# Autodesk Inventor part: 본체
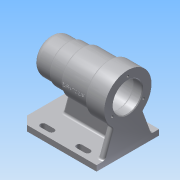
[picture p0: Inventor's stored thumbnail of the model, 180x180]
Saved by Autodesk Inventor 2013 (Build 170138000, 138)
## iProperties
Created: 2017-09
Part Number: 본체
Material: 알루미늄 6061
Document SubType Name: Modeling
Designer: Administrator
Density: 2.71 g/cm^3
Mass: 693.622 g
Surface Area: 713.941 cm^2
Volume: 255.949 cm^3
Author: Administrator
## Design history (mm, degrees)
sketch "스케치1"
  geometry: L1 (-56, 0)-(56, 0); L2 (-56, 0)-(-56, 25); L3 (-56, 25)-(-31, 25); L4 (-31, 25)-(-31, 27); L5 (-31, 27)-(-11, 27); L6 (-11, 27)-(-11, 30); L7 (-11, 30)-(28, 30); L8 (28, 30)-(28, 34); L9 (28, 34)-(56, 34); L10 (56, 34)-(56, 0); 2 further points
  constraints: 20 end point, 7 parallel, 2 perpendicular, 1 coincident, 1 horizontal, 1 midpoint
  dimensions: "d0" = 112 distance of L1.start L1.end; "d3" = 25 distance of L2.end L3.end; "d4" = 45 distance between parallel lines of L6 L2; "d5" = 84 distance between parallel lines of L8 L2; "d6" = 50 diameter of L3 L1; "d7" = 54 diameter of L5 L1; "d8" = 60 diameter of L7 L1; "d9" = 68 diameter of L9 L1
revolve "회전1" sketch "스케치1" stored, may be unused: angle "d10" = 90 deg
node "작업 평면1"
sketch "스케치2"
  geometry: L1 (-56, 45)-(56, 45); L2 (56, 45)-(56, -45); L3 (56, -45)-(-56, -45); L4 (-56, -45)-(-56, 45); L5 (-56, 34)-(-56, -34) reference; 2 further points
  constraints: 8 end point, 2 midpoint, 2 parallel, 1 horizontal, 1 perpendicular
  dimensions: "d12" = 90 distance between parallel lines of L3 L1; "d14" = 112 distance between parallel lines of L2 L4
extrude "돌출1" join sketch "스케치2" distance "d15" = 8; taper "d16" = 0 deg
sketch "스케치3"
  geometry: L1 (90, 8)-(0, 8) reference; L2 (10, 8)-(23.1, 43.992); L3 (80, 8)-(66.9, 43.992); A1 r 34 centre (45, 70) between (23.1, 43.992) and (66.9, 43.992) reference; A2 r 34 centre (45, 70) between (23.1, 43.992) and (66.9, 43.992) reference; 1 further point
  constraints: 4 end point, 4 point on circle, 2 point on line
  dimensions: "d17" = 10 distance of L1.end L2.start; "d18" = 10 distance of L1.start L3.start; "d19" = 110 deg angle of L1 L2; "d20" = 110 deg angle of L1 L3
extrude "돌출2" join sketch "스케치3" distance "d21" = 8; taper "d22" = 0 deg
sketch "스케치4"
  geometry: L1 (-31, -27)-(-11, -27) reference; L2 (56, -62)-(-56, -62) reference; L3 (-24.622, -27)-(-34, -62); L4 (-11, -30)-(28, -30) reference; L5 (28, -34)-(48, -34) reference; L6 (48, -62)-(48, -26.008) reference; L7 (48, -26.008)-(48, -26.008) reference; L8 (48, -26.008)-(48, -62) reference; L9 (28, -34)-(28, 34) reference; L10 (28, -30)-(28, 30) reference; L11 (-11, -30)-(-11, 30) reference; 1 further point
  constraints: 2 end point, 2 point on line
  dimensions: "d25" = 22 distance of L2.end L3.end; "d26" = 105 deg angle of L2 L3
feature "리브1" sketch "스케치4" dims "d27" = 1, "d28" = 8, "d29" = 0, "d30" = 0, "d31" = 1, "d32" = 1
sketch "스케치5"
  geometry: C1 r 10.5 at (45, 70); 1 further point
  constraints: 1 centre point, 1 coincident
  dimensions: "d33" = 21 diameter of C1
extrude "돌출3" cut sketch "스케치5" distance "d35" = 106; taper "d36" = 0 deg
sketch "스케치6"
  geometry: C1 r 16 at (45, 70); 1 further point
  constraints: 1 centre point, 1 coincident
  dimensions: "d37" = 32 diameter of C1
extrude "돌출4" cut sketch "스케치6" distance "d39" = 103; taper "d40" = 0 deg
sketch "스케치7"
  geometry: C1 r 17.5 at (45, 70); 1 further point
  constraints: 1 centre point, 1 coincident
  dimensions: "d41" = 35 diameter of C1
extrude "돌출5" cut sketch "스케치7" distance "d43" = 99; taper "d44" = 0 deg
sketch "스케치8"
  geometry: C1 r 10.5 at (45, 70) reference; C2 r 21 at (45, 70); 1 further point
  constraints: 1 centre point, 1 coincident
  dimensions: "d45" = 42 diameter of C2
extrude "돌출6" cut sketch "스케치8" distance "d47" = 81; taper "d48" = 0 deg
sketch "스케치9"
  geometry: C1 r 27 at (45, 70) reference; C2 r 24 at (45, 70); 1 further point
  constraints: 1 centre point, 1 coincident
  dimensions: "d49" = 48 diameter of C2
extrude "돌출7" cut sketch "스케치9" distance "d51" = 69; taper "d52" = 0 deg
sketch "스케치10"
  geometry: C1 r 10.5 at (45, 70) reference; C2 r 21 at (45, 70); C3 r 24 at (45, 70) reference; 1 further point
  constraints: 1 centre point, 1 coincident
  dimensions: "d53" = 42 diameter of C2
extrude "돌출8" join sketch "스케치10" distance "d55" = 15; taper "d56" = 0 deg
sketch "스케치11" dims "d57" = 52
  geometry: 3 further points
  constraints: 2 vertical alignment, 1 coincident, 2 other
hole "구멍1" sketch "스케치11" at (45, 96) diameter "d59" = 3.242; stored, may be unused: countersink angle "d63" = 90 deg, drill point angle "d65" = 120 deg; dims "d60" = 8, "d61" = 4, "d62" = 2, "d64" = 11
chamfer "모따기1" distance "d69" = 12; stored, may be unused: second distance "d70" = 2, angle "d71" = 45 deg
sketch "스케치12"
  geometry: L1 (20, 38)-(32, 38); L2 (32, 30)-(20, 30); L3 (56, 45)-(56, -45) reference; L4 (-32, 38)-(-20, 38); L5 (-20, 30)-(-32, 30); A1 r 4 centre (32, 34) between (32, 30) and (32, 38); A2 r 4 centre (20, 34) between (20, 38) and (20, 30); A3 r 4 centre (-20, 34) between (-20, 30) and (-20, 38); A4 r 4 centre (-32, 34) between (-32, 38) and (-32, 30); 1 further point
  constraints: 8 end point, 8 point on circle, 8 tangent, 4 centre point, 2 horizontal, 2 parallel, 1 horizontal alignment
  dimensions: "d72" = 12 distance of A1.centre A2.centre; "d74" = 8 distance between parallel lines of L2 L1; "d75" = 34 vertical distance of point (0, 0) A1.centre; "d76" = 24 distance from line of L3 A1.centre; "d77" = 12 distance of A3.centre A4.centre; "d78" = 8 distance between parallel lines of L5 L4; "d79" = 40 distance of A2.centre A3.centre
extrude "돌출9" cut sketch "스케치12" stored distance "d80" = 15; taper "d81" = 0 deg
fillet "모깎기1" dims "d82" = 0.3
fillet "모깎기2" dims "d83" = 3
chamfer "모따기2" distance "d84" = 1; stored, may be unused: second distance "d85" = 2, angle "d86" = 45 deg
fillet "모깎기3" dims "d87" = 3
fillet "모깎기4" dims "d88" = 3
fillet "모깎기5" dims "d89" = 9
fillet "모깎기6" dims "d90" = 3
node "작업 평면2"
sketch "스케치13"
  geometry: L1 (47.5, 34)-(47.5, -25.254) reference; 3 further points
  constraints: 1 coincident, 1 horizontal alignment, 1 other
  dimensions: "d91" = 48 distance from line of point (-0.5, 0) L1
feature "엠보싱1" sketch "스케치13" dims "d92" = 0.5, "d93" = 0
fillet "모깎기8" dims "d95" = 3
fillet "모깎기9" dims "d96" = 0.3
fillet "모깎기10" dims "d97" = 3
node "솔리드1"
pattern_circular "원형 패턴1" dims angle "d67" = 360 deg
mirror "대칭1"
node "투영된 루프1"
node "투영된 루프2"
node "투영된 루프3"
